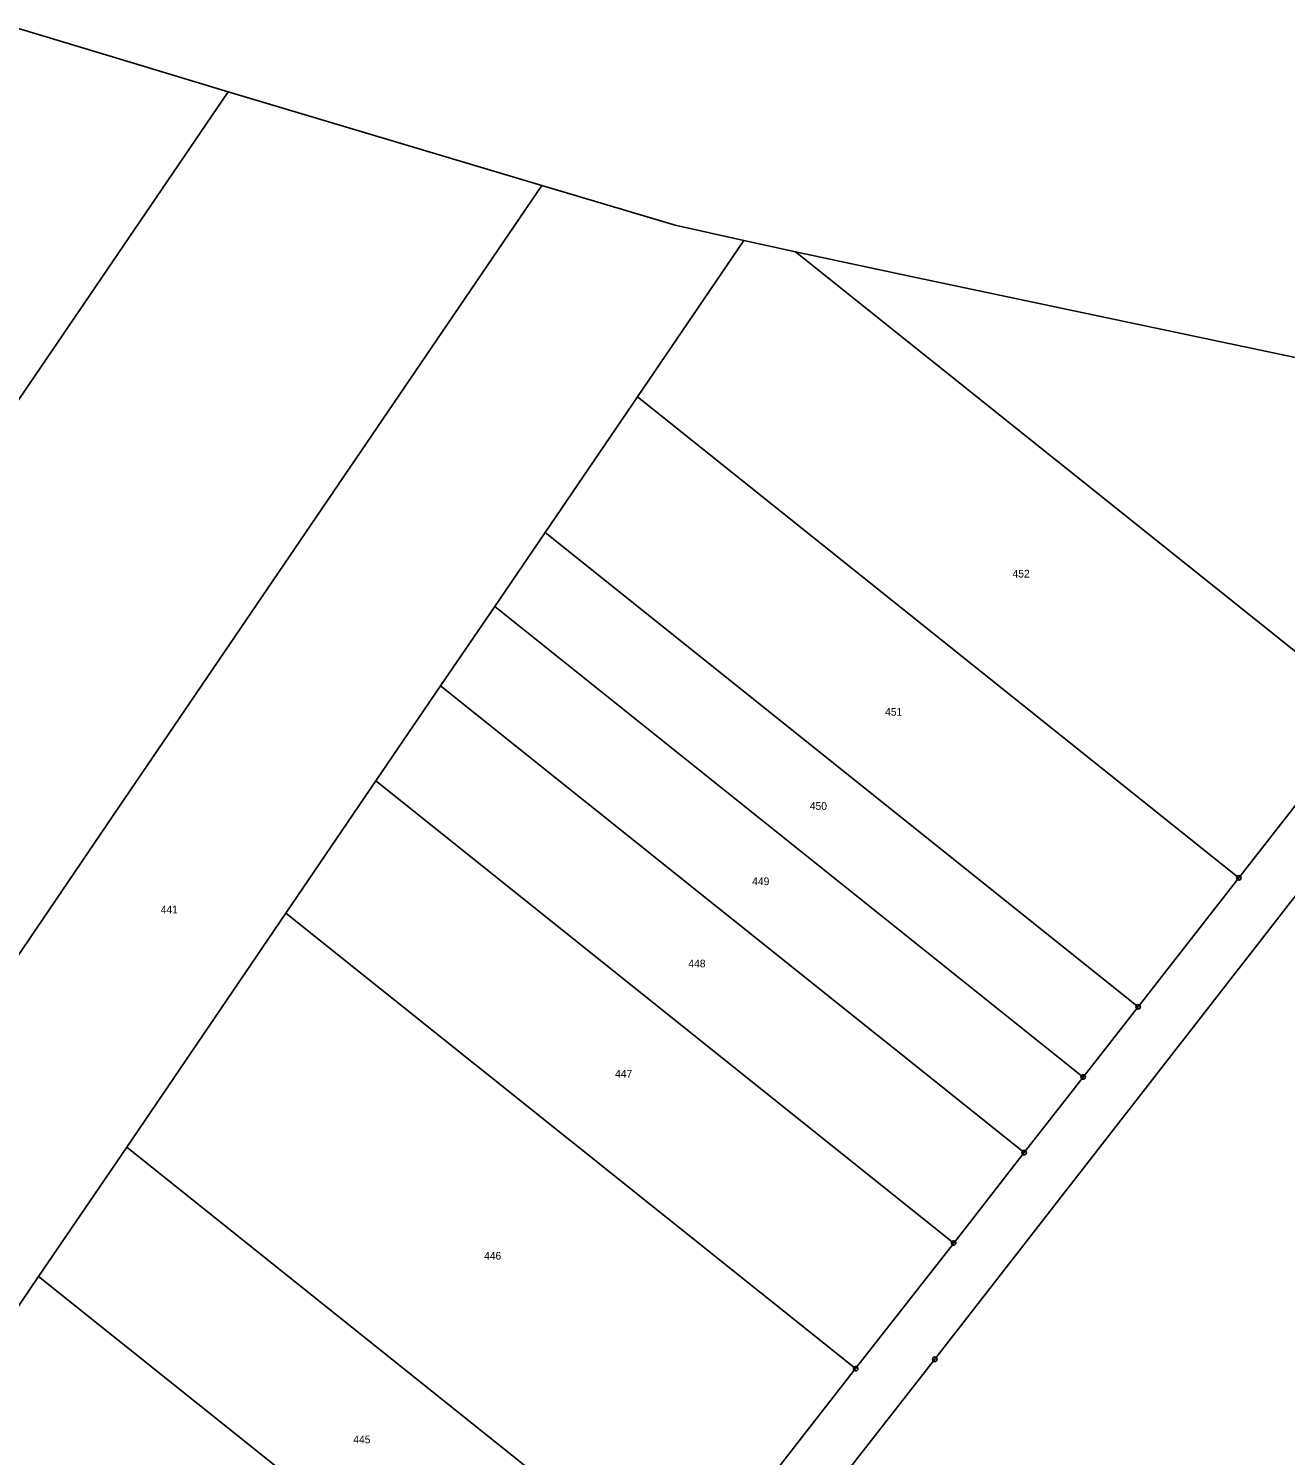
# Model space of a CAD drawing. Extents: x -759947 to -757003, y -1019641 to -1017100.
# Drawn here: x -758651.3 to -758373.5, y -1017872.8 to -1017557.2 of the extents above; entities that cross this region are included whole.
import ezdxf

# ---------------------------------------------------------------- set-up
doc = ezdxf.new("R2010")
doc.units = 0
doc.header["$LTSCALE"] = 0.68
doc.layers.add('1', color=7, linetype='Continuous', lineweight=25)
doc.layers.add('8', color=7, linetype='Continuous', lineweight=25)
doc.layers.add('2', color=7, linetype='Continuous')

msp = doc.modelspace()

# ---------------------------------------------------------------- linework, layer by layer
at = {"layer": '1'}
for p, q in [((-758628.85, -1017564.7), (-758653.58, -1017557.23)), ((-758607.23, -1017571.24), (-758628.85, -1017564.7)), ((-758693.95, -1017698.67), (-758607.23, -1017571.24)), ((-758607.23, -1017571.24), (-758537.86, -1017591.95)), ((-758537.86, -1017591.95), (-758632.5, -1017731.01)), ((-758537.86, -1017591.95), (-758508.4, -1017600.69)), ((-758508.4, -1017600.69), (-758493.21, -1017604.09)), ((-758516.75, -1017638.67), (-758493.21, -1017604.09)), ((-758493.21, -1017604.09), (-758481.81, -1017606.64)), ((-758481.81, -1017606.64), (-758354.99, -1017708.1)), ((-758456.27, -1017612.03), (-758481.81, -1017606.64)), ((-758425.51, -1017618.53), (-758456.27, -1017612.03)), ((-758395.42, -1017624.89), (-758425.51, -1017618.53)), ((-758356.92, -1017633.02), (-758395.42, -1017624.89)), ((-758537.17, -1017668.68), (-758516.75, -1017638.67)), ((-758516.75, -1017638.67), (-758383.81, -1017745.03)), ((-758548.29, -1017685.02), (-758537.17, -1017668.68)), ((-758406.07, -1017773.56), (-758537.17, -1017668.68)), ((-758560.26, -1017702.61), (-758548.29, -1017685.02)), ((-758548.29, -1017685.02), (-758418.2, -1017789.1)), ((-758574.56, -1017723.63), (-758560.26, -1017702.61)), ((-758431.25, -1017805.82), (-758560.26, -1017702.61)), ((-758383.81, -1017745.03), (-758354.99, -1017708.1)), ((-758594.44, -1017752.83), (-758574.56, -1017723.63)), ((-758574.56, -1017723.63), (-758446.84, -1017825.81)), ((-758632.5, -1017731.01), (-758727.13, -1017870.06)), ((-758356.83, -1017730.38), (-758451, -1017851.51)), ((-758406.07, -1017773.56), (-758383.81, -1017745.03)), ((-758629.65, -1017804.58), (-758594.44, -1017752.83)), ((-758468.51, -1017853.58), (-758594.44, -1017752.83)), ((-758418.2, -1017789.1), (-758406.07, -1017773.56)), ((-758431.25, -1017805.82), (-758418.2, -1017789.1)), ((-758649.12, -1017833.18), (-758629.65, -1017804.58)), ((-758629.65, -1017804.58), (-758506.9, -1017902.78)), ((-758446.84, -1017825.81), (-758431.25, -1017805.82)), ((-758468.51, -1017853.58), (-758446.84, -1017825.81)), ((-758693.19, -1017897.94), (-758649.12, -1017833.18)), ((-758649.12, -1017833.18), (-758596.28, -1017875.45)), ((-758451, -1017851.51), (-758492.6, -1017904.67)), ((-758506.9, -1017902.78), (-758468.51, -1017853.58))]:
    msp.add_line(p, q, dxfattribs=at)
at = {"layer": '8'}
for centre, radius in [((-758383.81, -1017745.0299), 0.5), ((-758383.81, -1017745.0299), 0.0303), ((-758406.07, -1017773.5599), 0.5), ((-758406.07, -1017773.5599), 0.0303), ((-758418.2, -1017789.0999), 0.5), ((-758418.2, -1017789.0999), 0.0303), ((-758431.25, -1017805.8199), 0.5), ((-758431.25, -1017805.8199), 0.0303), ((-758446.84, -1017825.8099), 0.5), ((-758446.84, -1017825.8099), 0.0303), ((-758451, -1017851.5099), 0.5), ((-758451, -1017851.5099), 0.0303), ((-758468.51, -1017853.5799), 0.5), ((-758468.51, -1017853.5799), 0.0303)]:
    msp.add_circle(centre, radius, dxfattribs=at)

# ---------------------------------------------------------------- texts
at = {"layer": '2'}
for s, p in [('452', (-758433.83, -1017678.635)), ('451', (-758461.99, -1017709.195)), ('450', (-758478.64, -1017730.005)), ('449', (-758491.38, -1017746.655)), ('441', (-758622.13, -1017752.915)), ('448', (-758505.49, -1017764.845)), ('447', (-758521.69, -1017789.225)), ('446', (-758550.65, -1017829.485)), ('445', (-758579.56, -1017870.095))]:
    msp.add_text(s, height=1.7, dxfattribs=at).set_placement(p)

doc.saveas('drawing.dxf')
